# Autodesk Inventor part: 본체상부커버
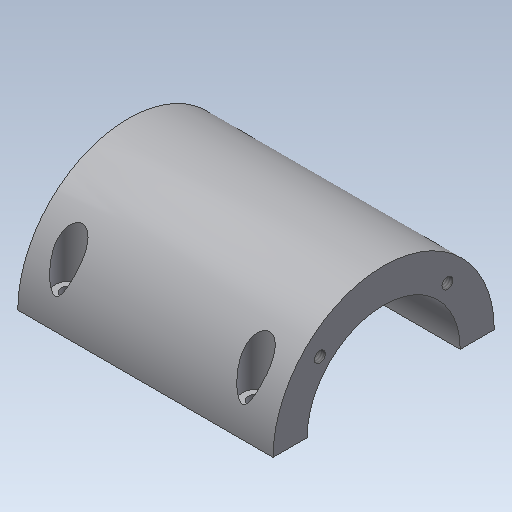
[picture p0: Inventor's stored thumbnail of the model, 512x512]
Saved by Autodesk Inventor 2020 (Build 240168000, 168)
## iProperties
Created: 2015-12
Part Number: 본체상부커버
Material: 알루미늄 6061
Document SubType Name: Modeling
Designer: mduedu
Density: 2.71 g/cm^3
Appearance: 알루미늄 - 평지
Mass: 168.089 g
Surface Area: 176.023 cm^2
Volume: 62.0254 cm^3
Author: mduedu
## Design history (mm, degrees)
sketch "스케치1"
  geometry: L1 (45, 40)-(-45, 40); L2 (-45, 40)-(-45, -40); L3 (-45, -40)-(45, -40); L4 (45, -40)-(45, 40); L5 (45, 40)-(-45, -40); L6 (-45, 40)-(45, -40); 2 further points
  constraints: 12 end point, 2 midpoint, 2 parallel, 1 coincident, 1 horizontal, 1 perpendicular, 3 other
  dimensions: "d0" = 90 distance of L2.end L3.end; "d2" = 80 distance of L1.end L2.end
extrude "돌출1" new body sketch "스케치1" distance "d3" = 10; taper "d4" = 0 deg
sketch "스케치2"
  geometry: C1 r 32.5 at (80, 0); 1 further point
  constraints: 1 centre point
  dimensions: "d5" = 65 diameter of C1; "d116" = 80 distance of point (0, 0) C1.centre
extrude "돌출2" join sketch "스케치2" stored distance "d7" = 75; taper "d8" = 0 deg
sketch "스케치3"
  geometry: L1 (-27.5, -20)-(27.5, -20); L2 (27.5, -20)-(27.5, 20); L3 (27.5, 20)-(-27.5, 20); L4 (-27.5, 20)-(-27.5, -20); L5 (-27.5, -20)-(27.5, 20); L6 (27.5, -20)-(-27.5, 20); 1 further point
  constraints: 12 end point, 2 midpoint, 2 parallel, 1 horizontal, 1 perpendicular
  dimensions: "d9" = 55 distance of L2.end L3.end; "d11" = 40 distance of L1.end L2.end
extrude "돌출3" new body sketch "스케치3" stored distance "d12" = 75; taper "d13" = 0 deg
fillet "모깎기1"
fillet "모깎기2"
feature "결합1"
  node "솔리드2"
sketch "스케치4"
  geometry: L1 (-37.5, 47.5)-(37.5, 47.5) reference; L2 (32.5, 47.5)-(40.208, 10); L3 (37.5, 47.5)-(37.5, 112.5) reference; L4 (60.208, 0)-(60.208, 10) reference; L5 (60.208, 10)-(-60.208, 10) reference; 1 further point
  constraints: 2 end point, 2 point on line
  dimensions: "d15" = 5 distance from line of L2.start L3; "d117" = 20 distance from line of L2.end L4
sketch "스케치5"
  geometry: L1 (10, 35.208)-(56.729, 22.687); L2 (0, 60.208)-(10, 60.208) reference; L3 (10, -60.208)-(10, 60.208) reference; 2 further points
  constraints: 2 end point, 1 point on line, 2 other
  dimensions: "d118" = 25 distance from line of L1.start L2; "d119" = 75 deg angle of L1 L3
feature "리브1" dims "d19" = 1, "d20" = 6, "d21" = 0, "d22" = 0, "d23" = 1, "d24" = 1
feature "리브2" dims "d25" = 1, "d26" = 6, "d27" = 0, "d28" = 0, "d29" = 1, "d30" = 1
fillet "모깎기4" dims "d31" = 2
fillet "모깎기5" dims "d32" = 2
fillet "모깎기6" dims "d33" = 2
sketch "스케치6"
  geometry: L1 (0, 0)-(-32.88, 32.88); L2 (0, 0)-(-46.5, 0); A1 r 46.5 centre (0, 0) between (-32.88, 32.88) and (-46.5, 0); 5 further points
  constraints: 4 end point, 2 coincident, 2 point on circle, 1 centre point, 1 horizontal, 5 other
  dimensions: "d120" = 93 diameter of A1; "d122" = 45 deg angle of L1 L2; "d126" = 360 deg dimension on point (0, 0) point (-32.88, 32.88) (derived)
hole "구멍1" sketch "스케치6" at (-32.88, 32.88), (-32.88, -32.88), (32.88, -32.88), (32.88, 32.88) diameter "d34" = 7; stored, may be unused: countersink angle "d38" = 90 deg, drill point angle "d40" = 118 deg; dims "d35" = 6, "d36" = 12, "d37" = 3, "d39" = 8
fillet "모깎기13" dims "d131" = 3
hole "구멍2" diameter "d44" = 45; stored, may be unused: countersink angle "d48" = 90 deg, drill point angle "d50" = 118 deg; dims "d42" = 10, "d43" = 10, "d45" = 6, "d46" = 4, "d47" = 2, "d49" = 8
sketch "스케치7" dims "d52" = 26.5
  geometry: L1 (0, 0)-(32.5, 0); L2 (0, 0)-(22.981, 22.981); A1 r 32.5 centre (0, 0) between (32.5, 0) and (22.981, 22.981) reference; 3 further points
  constraints: 4 end point, 2 point on circle, 1 coincident, 1 horizontal, 1 point on line, 3 other
  dimensions: "d51" = 45 deg angle of L2 L1
hole "구멍3" sketch "스케치7" at (18.738, 18.738) diameter "d54" = 3.242; stored, may be unused: countersink angle "d58" = 90 deg, drill point angle "d60" = 118 deg; dims "d55" = 8, "d56" = 4, "d57" = 2, "d59" = 10
sketch "스케치9"
  geometry: L1 (-75, -110)-(75, -110); L2 (75, -110)-(75, 0); L3 (75, 0)-(-75, 0); L4 (-75, 0)-(-75, -110); L5 (-60.208, -80)-(60.208, -80) reference; C1 r 32.5 at (0, 0) reference; 2 further points
  constraints: 8 end point, 2 parallel, 1 coincident, 1 horizontal, 1 midpoint, 1 perpendicular
  dimensions: "d148" = 30 distance between parallel lines of L5 L1; "d159" = 150 distance between parallel lines of L2 L4
extrude "돌출5" cut sketch "스케치9" extent not by distance; stored distance "d73" = 0; taper "d74" = 0 deg
sketch "스케치19"
  geometry: C1 r 1.244 at (-65, 5) reference; C2 r 1.244 at (-10, 5) reference; C3 r 1.244 at (-10, -50) reference; C4 r 1.244 at (-65, -50) reference; 1 further point
hole "구멍9" sketch "스케치19" at (-65, 5), (-10, 5), (-10, -50), (-65, -50) diameter "d160" = 4.5; stored, may be unused: countersink angle "d164" = 90 deg, drill point angle "d166" = 118 deg; dims "d161" = 6, "d162" = 4, "d163" = 2, "d165" = 8
node "작업 평면4"
sketch "스케치20"
  geometry: C1 r 2.25 at (-65, 5) reference; C2 r 2.25 at (-10, 5) reference; C3 r 2.25 at (-10, -50) reference; C4 r 2.25 at (-65, -50) reference; C5 r 4 at (-65, -50); C6 r 4 at (-10, -50); C7 r 4 at (-10, 5); C8 r 4 at (-65, 5); 1 further point
  constraints: 4 centre point, 4 coincident, 3 equal radius
  dimensions: "d168" = 8 diameter of C5
extrude "돌출9" cut sketch "스케치20" extent not by distance; stored distance "d169" = 10; taper "d170" = 0 deg
node "솔리드1"
mirror "대칭1"
mirror "대칭2"
pattern_circular "원형 패턴1" dims angle "d62" = 360 deg
mirror "대칭3"
node "참조1"
node "참조2"
node "참조3"
node "참조4"
other parameters: "d167" = -7
